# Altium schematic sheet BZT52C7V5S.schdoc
size 127 x 101 mm
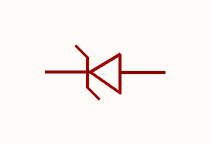
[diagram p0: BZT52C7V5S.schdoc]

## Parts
ZD?  bzt52c7v5s_c17284  [SOD-323_L1.8-W1.3-LS2.5-RD]  (value not drawn)

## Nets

Not connected (* = marked no-connect by the designer): ZD? 1(K) 2(A)

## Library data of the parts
ZD? = bzt52c7v5s_c17284: 二极管配置:1个独立式;稳压值(标称值):7.5V;稳压值(范围值):7V~7.9V;耗散功率(Pd):200mW;; Manufacturer: CJ(江苏长电/长晶); AddInBom: yes; ModelId: db63db13d9e342eb939127d413d6200b; ModelTransform: 104.3305,51.181,0,0,0,0,0,-0.004,0; Diode Configuration: 1个独立式; Zener Voltage(Nom): 7.5V; Reverse Leakage Current (Ir): 1uA; Pd - Power Dissipation: 200mW; Impedance(Zzt): 15Ω; Impedance(Zzk): 80Ω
